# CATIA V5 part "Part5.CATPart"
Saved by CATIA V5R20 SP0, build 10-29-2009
Part number: Part5
Bounding box of the stored display mesh (mm): x -400 to 150, y -79.813 to 429.814, z -80 to 80
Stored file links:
  E:\新建文件夹 (2)\Part5.CATPart
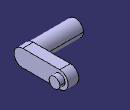
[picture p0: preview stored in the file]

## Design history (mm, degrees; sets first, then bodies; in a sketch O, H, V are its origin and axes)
Body1 (main body)
  Sketch1 on yz-plane, origin (0, 0, 0), H (0, 1, 0), V (0, 0, 1)
    arc A1 centre (0, 0) radius 80 from (0, 80) to (0, -80) ccw
    point P1 (0, 80)
    arc A2 centre (350, 0) radius 80 from (350, -80) to (350, 80) ccw
    point P2 (350, 0)
    line L1 (350, 80) -> (0, 80)
    line L2 (0, -80) -> (350, -80)
    point P4 (0, -80)
    coincidence: P1 V, P2 H, P4 V
    tangency: L1 A2, L2 A2
  Pad1: profile Sketch1, direction (1, 0, 0), length 100
  Sketch2 on end face of Pad1, origin (100, 0, 0), H (0, 1, 0), V (0, 0, 1)
    circle A1 centre (350, 0) radius 50
    point P1 (350, 0)
    coincidence: P1 H
  Pad2: profile Sketch2, direction (1, 0, 0), length 50
  Sketch3 on start face of Pad1, origin (0, 0, 0), H (0, -1, 0), V (0, 0, 1)
    circle A1 centre (0, 0) radius 75
  Pad3: profile Sketch3, direction (-1, 0, 0), length 400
